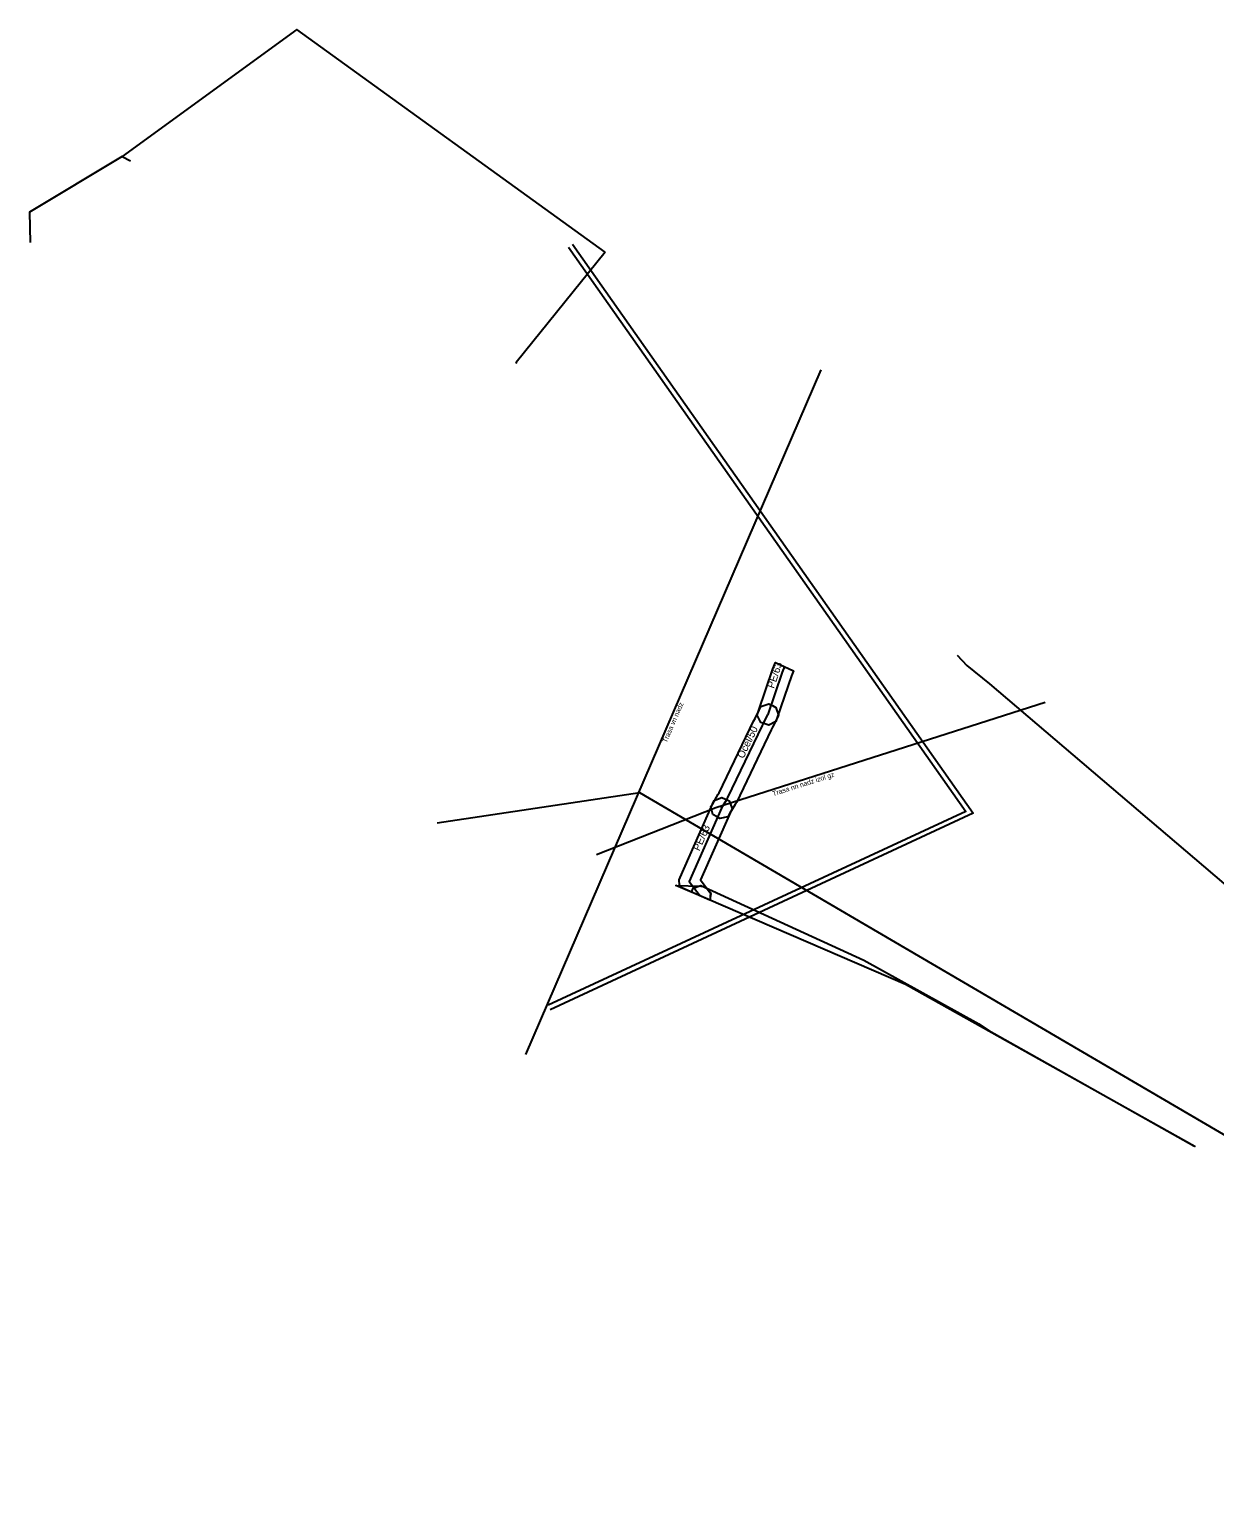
# Model space of a CAD drawing. Extents: x -743072 to -742584, y -978827 to -978325.
# Drawn here: x -743071.9 to -742951.5, y -978475.4 to -978325 of the extents above; entities that cross this region are included whole.
import ezdxf

# ---------------------------------------------------------------- set-up
doc = ezdxf.new("R2010")
doc.units = 0
for name, color, linetype in [('IS_CETIN_sdělovací kabel_nadz', 7, 'Continuous'), ('IS_CEZ_NN_nadz', 7, 'Continuous'), ('IS_CEZ_VN_nadz', 7, 'Continuous'), ('IS_GasNet_ochr pasmo', 7, 'Continuous'), ('IS_GasNet_plyn STL', 7, 'Continuous'), ('IS_Obec_kabel VO_nadz', 7, 'Continuous'), ('IS_popis_CEZ', 7, 'Continuous'), ('IS_popis_GasNet', 7, 'Continuous'), ('IS_ScVK_Vodovod', 7, 'Continuous')]:
    doc.layers.add(name, color=color, linetype=linetype)

msp = doc.modelspace()

# ---------------------------------------------------------------- linework, layer by layer
at = {"layer": 'IS_CETIN_sdělovací kabel_nadz'}
for points in [[(-743013.4, -978347.6), (-743044.71, -978325), (-743062.47, -978337.9)], [(-743062.47, -978337.9), (-743071.863, -978343.527), (-743071.801, -978346.623)], [(-743062.47, -978337.9), (-743061.618, -978338.31)], [(-743013.4, -978347.6), (-743022.437, -978358.811), (-743022.487, -978358.898)], [(-743017.13, -978347.08), (-742976.78, -978404.391), (-743019.189, -978424.09)]]:
    msp.add_lwpolyline(points, dxfattribs=at)
at = {"layer": 'IS_CEZ_NN_nadz'}
msp.add_lwpolyline([(-742968.7, -978393.33), (-743002.17, -978404.04), (-743014.29, -978408.8)], dxfattribs=at)
at = {"layer": 'IS_CEZ_VN_nadz'}
msp.add_lwpolyline([(-742991.512, -978359.561), (-743021.5, -978429.08)], dxfattribs=at)
at = {"layer": 'IS_GasNet_ochr pasmo'}
for points in [[(-742996.368, -978389.922), (-742996.102, -978389.266), (-742994.286, -978390.111), (-742994.492, -978390.618), (-742995.922, -978394.869), (-742996.054, -978395.262), (-742996.796, -978395.63), (-742997.189, -978395.498), (-742997.582, -978395.366), (-742997.95, -978394.624), (-742997.818, -978394.231)], [(-743002.66, -978403.898), (-743002.446, -978403.543), (-743001.913, -978402.66), (-743001.831, -978402.524), (-742998.329, -978395.242), (-742998.185, -978394.951), (-742997.766, -978394.106), (-742997.582, -978393.735), (-742996.797, -978393.47), (-742996.426, -978393.654), (-742996.055, -978393.838), (-742995.79, -978394.623), (-742995.974, -978394.994), (-742996.393, -978395.839), (-742996.531, -978396.118), (-743000.069, -978403.476), (-743000.201, -978403.694), (-743000.734, -978404.577), (-743000.948, -978404.932), (-743001.752, -978405.13), (-743002.107, -978404.916), (-743002.462, -978404.702)], [(-743002.774, -978413.395), (-743005.633, -978412.161), (-743005.674, -978412.108), (-743005.84, -978411.891), (-743005.906, -978411.347), (-743005.795, -978411.096), (-743002.505, -978403.656), (-743002.337, -978403.277), (-743001.565, -978402.978), (-743001.186, -978403.145), (-743000.807, -978403.313), (-743000.508, -978404.085), (-743000.675, -978404.464), (-743003.726, -978411.362), (-743002.936, -978412.392), (-743002.684, -978412.72)], [(-743002.731, -978413.037), (-743002.744, -978413.408), (-743006.221, -978411.908), (-743003.693, -978412.001), (-743003.279, -978412.016), (-743002.716, -978412.623)], [(-742982.914, -978421.964), (-743004.642, -978412.589), (-743004.639, -978412.583), (-743004.466, -978412.206), (-743003.69, -978411.918), (-743003.313, -978412.091), (-742987.119, -978419.517), (-742975.438, -978425.976), (-742974.425, -978426.658), (-742953.604, -978438.363), (-742953.514, -978438.421)]]:
    msp.add_lwpolyline(points, close=True, dxfattribs=at)
at = {"layer": 'IS_GasNet_plyn STL'}
for points in [[(-742995.194, -978389.688), (-742995.43, -978390.27), (-742996.87, -978394.55)], [(-743001.59, -978404.06), (-743001.057, -978403.177), (-743000.95, -978403), (-742997.43, -978395.68), (-742997.289, -978395.395), (-742996.87, -978394.55)], [(-743001.59, -978404.06), (-743004.88, -978411.5), (-743003.75, -978412.974)]]:
    msp.add_lwpolyline(points, dxfattribs=at)
at = {"layer": 'IS_Obec_kabel VO_nadz'}
msp.add_lwpolyline([(-743016.721, -978346.792), (-742976.027, -978404.592), (-743018.978, -978424.543)], dxfattribs=at)
at = {"layer": 'IS_ScVK_Vodovod'}
for points in [[(-742977.649, -978388.53), (-742976.664, -978389.595), (-742974.357, -978391.436), (-742948.728, -978413.286), (-742927.308, -978430.422), (-742902.077, -978450.432), (-742883.738, -978468.975), (-742876.53, -978475.383)], [(-742925.438, -978451.947), (-743009.893, -978402.51), (-743030.46, -978405.59)]]:
    msp.add_lwpolyline(points, dxfattribs=at)

# ---------------------------------------------------------------- texts
at = {"layer": 'IS_popis_CEZ'}
for s, rotation, p in [('Trasa vn nadz', 66.66643, (-743007.156, -978397.468)), ('Trasa nn nadz izol gz', 17.74405, (-742996.329, -978402.853))]:
    msp.add_text(s, height=0.5, rotation=rotation, dxfattribs=at).set_placement(p)
at = {"layer": 'IS_popis_GasNet'}
for s, rotation, p in [('PE/63', 71.40456, (-742996.266, -978391.96)), ('Ocel/50', 64.31829, (-742999.363, -978399.085)), ('PE/63', 66.14478, (-743003.831, -978408.475))]:
    msp.add_text(s, height=0.75, rotation=rotation, dxfattribs=at).set_placement(p)

doc.saveas('drawing.dxf')
